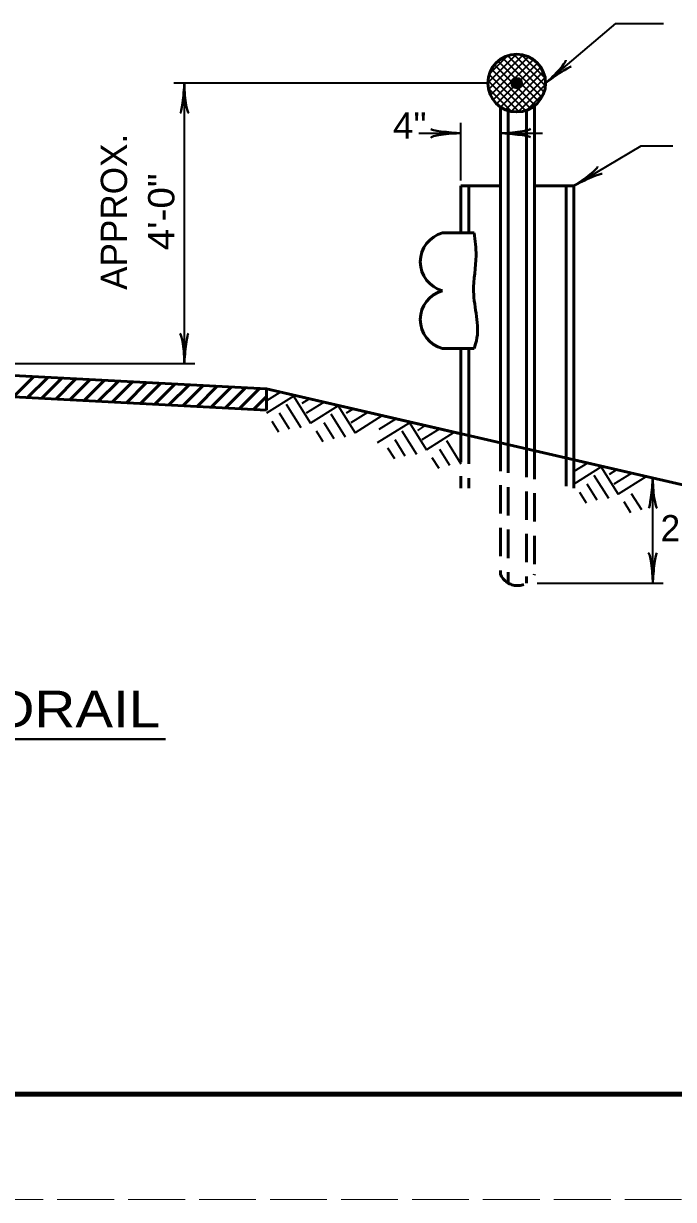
# Model space of a CAD drawing. Extents: x -54 to 626, y -41 to 399.
# Drawn here: x 117.5 to 179.4, y -41.3 to 70.7 of the extents above; entities that cross this region are included whole.
import ezdxf
from ezdxf.enums import TextEntityAlignment as Align

# ---------------------------------------------------------------- set-up
doc = ezdxf.new("R2010")
doc.units = 0
doc.header["$LTSCALE"] = 0.9
doc.linetypes.add('LONG_DASHED', pattern=[7.5, 6, -1.5])
doc.linetypes.add('MEDIUM_DASHED', pattern=[4.5, 3, -1.5])
doc.layers.add('1', color=7, linetype='Continuous', lineweight=35)
doc.layers.add('61', color=7, linetype='Continuous', lineweight=35)

msp = doc.modelspace()

# ---------------------------------------------------------------- hatches: boundary and pattern name
at = {"layer": '1'}
msp.add_hatch(color=256, dxfattribs=at).paths.add_polyline_path([(164.964, 64.9796, 1), (163.964, 64.9796, 1)])

# ---------------------------------------------------------------- linework, layer by layer
for p, q in [((161.7149, 65.008), (164.4343, 67.7274)), ((161.7842, 64.3702), (165.0726, 67.6585)), ((161.8652, 65.8653), (163.5791, 67.5793)), ((161.9649, 63.8438), (165.5998, 67.4786)), ((162.2211, 63.3928), (166.0515, 67.2232)), ((166.8579, 63.6317), (163.117, 67.3726)), ((167.0724, 64.1243), (163.6083, 67.5883)), ((167.1966, 64.7073), (164.1904, 67.7133)), ((167.1702, 65.4407), (164.925, 67.6859)), ((165.7922, 62.5759), (162.0594, 66.3088)), ((166.2133, 62.862), (162.3472, 66.7282)), ((162.5482, 63.0129), (166.4304, 66.8951)), ((166.5676, 63.2148), (162.6985, 67.084)), ((162.9379, 62.6955), (166.7488, 66.5063)), ((166.5714, 66.7737), (166.2742, 67.0709)), ((161.714, 64.9796), (131.843, 64.9796)), ((132.843, 38.2649), (132.843, 64.9796)), ((164.7103, 62.2437), (161.7292, 65.2248)), ((165.2973, 62.3638), (161.8485, 65.8127)), ((163.3981, 62.4485), (166.9946, 66.0451)), ((163.9414, 62.2847), (167.1589, 65.5023)), ((163.9671, 62.2798), (161.7643, 64.4826)), ((164.6018, 62.238), (167.2062, 64.8424)), ((165.5366, 62.4877), (167.0281, 63.9792)), ((159.1594, 55.7112), (159.1594, 61.2112)), ((155.1594, 60.2112), (159.1594, 60.2112)), ((162.9094, 60.2112), (166.9094, 60.2112)), ((96.2767, 38.2649), (133.843, 38.2649)), ((141.9227, 35.5312), (140.6464, 34.7338)), ((143.3063, 35.2118), (140.6464, 33.5497)), ((143.2088, 35.2343), (144.8576, 32.5958)), ((144.6899, 34.8924), (144.0137, 34.4532)), ((142.5252, 34.4069), (143.9236, 32.1957)), ((146.093, 34.5685), (144.4379, 33.5343)), ((147.4766, 34.2491), (144.8576, 32.5958)), ((147.4766, 34.2491), (149.0803, 31.6825)), ((148.8602, 33.9296), (148.2365, 33.5399)), ((150.2632, 33.6057), (148.6802, 32.6164)), ((141.1669, 32.791), (141.8159, 31.7791)), ((141.861, 33.575), (142.8202, 32.0398)), ((146.1033, 32.6572), (147.0626, 31.122)), ((146.7674, 33.4891), (148.1464, 31.2823)), ((151.6469, 33.2862), (149.0803, 31.6825)), ((154.3167, 32.6699), (151.1744, 30.7064)), ((152.9331, 32.9893), (151.3499, 32.0001)), ((154.2192, 32.6924), (155.8679, 30.0539)), ((145.3897, 31.8777), (146.0342, 30.8463)), ((153.5356, 31.865), (154.934, 29.6537)), ((155.7002, 32.3505), (155.0242, 31.9113)), ((157.1033, 32.0265), (155.4483, 30.9923)), ((158.487, 31.7071), (155.8679, 30.0539)), ((152.1772, 30.2491), (152.8262, 29.2372)), ((152.8714, 31.0331), (153.8307, 29.4979)), ((157.7778, 30.9472), (159.1594, 28.7362)), ((156.4001, 29.3357), (157.0446, 28.3043)), ((157.1137, 30.1152), (158.0729, 28.5801)), ((171.1866, 28.7752), (169.9094, 27.9772)), ((172.5702, 28.4558), (169.9094, 26.7933)), ((172.4727, 28.4783), (174.1214, 25.8397)), ((173.9537, 28.1363), (173.2777, 27.6973)), ((171.7891, 27.6509), (173.1875, 25.4397)), ((175.3569, 27.8124), (173.7018, 26.7782)), ((176.7405, 27.493), (174.1214, 25.8397)), ((177.4094, 17.3654), (177.4094, 27.3796)), ((170.4307, 26.035), (171.0797, 25.0231)), ((171.1249, 26.819), (172.0842, 25.2838)), ((175.3672, 25.9011), (176.3264, 24.366)), ((174.6536, 25.1217), (175.298, 24.0902)), ((166.4094, 17.3654), (178.4094, 17.3654))]:
    msp.add_line(p, q, dxfattribs=at)
at = {"layer": '1', "lineweight": 53}
for p, q in [((166.1594, 29.9768), (166.1594, 62.8144)), ((162.9094, 30.7272), (162.9094, 62.7112)), ((163.6594, 30.554), (163.6594, 62.3499)), ((165.4094, 30.15), (165.4094, 62.3972)), ((159.1594, 55.2112), (162.9094, 55.2112)), ((159.1594, 50.7112), (159.1594, 55.2112)), ((159.9094, 50.7112), (159.9094, 55.2112)), ((166.1594, 55.2112), (169.9094, 55.2112)), ((169.1594, 29.2843), (169.1594, 55.2112)), ((169.9094, 29.1111), (169.9094, 55.2112)), ((157.4094, 50.7112), (160.4094, 50.7112)), ((157.4094, 39.7112), (160.4094, 39.7112)), ((159.1594, 31.5929), (159.1594, 39.7112)), ((159.9094, 31.4198), (159.9094, 39.7112)), ((93.8158, 38.3083), (140.6464, 35.8671)), ((116.5869, 35.1065), (118.5019, 37.0214)), ((140.6464, 33.8456), (93.8156, 36.2998)), ((117.9307, 35.0361), (119.846, 36.9513)), ((119.2745, 34.9657), (121.1902, 36.8813)), ((120.6183, 34.8952), (122.5343, 36.8113)), ((121.9621, 34.8248), (123.8785, 36.7412)), ((123.3059, 34.7543), (125.2226, 36.6711)), ((124.6497, 34.6839), (126.5667, 36.601)), ((125.9934, 34.6135), (127.9109, 36.531)), ((127.3372, 34.5431), (129.2551, 36.4609)), ((128.681, 34.4727), (130.5992, 36.3908)), ((130.0248, 34.4023), (131.9433, 36.3207)), ((131.3686, 34.3318), (133.2875, 36.2507)), ((132.7124, 34.2614), (134.6317, 36.1806)), ((134.0562, 34.191), (135.9758, 36.1106)), ((135.4, 34.1205), (137.3199, 36.0405)), ((136.7438, 34.0501), (138.6641, 35.9704)), ((138.0876, 33.9797), (140.0083, 35.9003)), ((140.6455, 35.8672), (159.1594, 31.5929)), ((140.6464, 33.8456), (140.6464, 35.8671)), ((140.6464, 35.867), (176.5165, 27.5857)), ((139.4313, 33.9093), (140.6464, 35.1243))]:
    msp.add_line(p, q, dxfattribs=at)
at = {"layer": '1', "linetype": 'MEDIUM_DASHED', "lineweight": 53}
for p, q in [((159.1594, 31.5929), (159.1594, 26.4198)), ((159.9094, 31.4198), (159.9094, 26.4198)), ((162.9094, 30.7272), (162.9094, 18.2272)), ((163.6594, 30.554), (163.6594, 17.3654)), ((165.4094, 30.15), (165.4094, 17.3654)), ((166.1594, 29.9768), (166.1594, 18.2272)), ((169.1594, 29.2843), (169.1594, 26.4198)), ((169.9094, 29.1111), (169.9094, 26.4198))]:
    msp.add_line(p, q, dxfattribs=at)
at = {"layer": '1', "lineweight": 40}
msp.add_line((34.2753, 2.5087), (131.065, 2.5087), dxfattribs=at)
at = {"layer": '1'}
for points in [[(167.214, 64.9796), (173.8878, 70.655), (178.4295, 70.655)], [(169.9094, 55.2112), (176.294, 59.0048), (179.3203, 59.0048)]]:
    msp.add_lwpolyline(points, dxfattribs=at)
at = {"layer": '1', "lineweight": 53}
msp.add_lwpolyline([(169.9094, 29.1112), (176.5165, 27.5857), (212.636, 19.2467)], dxfattribs=at)
msp.add_circle((164.464, 64.9796), 2.75, dxfattribs=at)
at = {"layer": '1'}
msp.add_circle((164.464, 64.9796), 0.5, dxfattribs=at)
at = {"layer": '1', "lineweight": 53}
for centre in [(158.1376, 47.9612), (158.1376, 42.4612)]:
    msp.add_arc(centre, 2.8448, 104.83216, 255.16784, dxfattribs=at)
at = {"layer": '1', "linetype": 'MEDIUM_DASHED', "lineweight": 53}
msp.add_arc((164.5344, 18.8842), 1.7528, 202.01371, 337.98629, dxfattribs=at)
at = {"layer": '1', "lineweight": 40}
for centre, major_axis, ratio, start_param, end_param in [((167.8663, 65.897), (-1.2592, -1.2758), 0.122415, 0.89635335, 3.14159265), ((167.8663, 65.897), (-1.2592, -1.2758), 0.122415, 0.89635335, 3.14159265), ((168.2047, 65.5443), (-1.4518, -1.0041), 0.07063, 3.14071475, 5.41810995), ((168.2047, 65.5443), (-1.4518, -1.0041), 0.07063, 3.14071475, 5.41810995), ((132.6314, 63.8591), (0.1757, 1.7565), 0.07063, 3.14071475, 5.41810995), ((133.1193, 63.8884), (-0.1562, 1.7857), 0.122415, 0.89635335, 3.14159265), ((158.0389, 60.4228), (1.7565, -0.1757), 0.07063, 3.14071475, 5.41810995), ((158.0389, 60.4228), (1.7565, -0.1757), 0.07063, 3.14071475, 5.41810995), ((164.0006, 60.4875), (-1.7857, -0.1562), 0.122415, 0.89635335, 3.14159265), ((158.0682, 59.9349), (1.7857, 0.1562), 0.122415, 0.89635335, 3.14159265), ((158.0682, 59.9349), (1.7857, 0.1562), 0.122415, 0.89635335, 3.14159265), ((164.0299, 59.9996), (-1.7565, 0.1757), 0.07063, 3.14071475, 5.41810995), ((170.7064, 56.0061), (-1.4554, -1.0464), 0.122415, 0.89635335, 3.14159265), ((170.9808, 55.6016), (-1.5997, -0.7462), 0.07063, 3.14071475, 5.41810995), ((132.5667, 39.3561), (0.1562, -1.7857), 0.122415, 0.89635335, 3.14159265), ((133.0546, 39.3854), (-0.1757, -1.7565), 0.07063, 3.14071475, 5.41810995), ((177.1978, 26.2591), (0.1757, 1.7565), 0.07063, 3.14071475, 5.41810995), ((177.1978, 26.2591), (0.1757, 1.7565), 0.07063, 3.14071475, 5.41810995), ((177.6857, 26.2884), (-0.1562, 1.7857), 0.122415, 0.89635335, 3.14159265), ((177.6857, 26.2884), (-0.1562, 1.7857), 0.122415, 0.89635335, 3.14159265), ((177.1331, 18.4566), (0.1562, -1.7857), 0.122415, 0.89635335, 3.14159265), ((177.621, 18.4859), (-0.1757, -1.7565), 0.07063, 3.14071475, 5.41810995)]:
    msp.add_ellipse(centre, major_axis=major_axis, ratio=ratio, start_param=start_param, end_param=end_param, dxfattribs=at)
at = {"layer": '1', "lineweight": 53}
msp.add_spline([(160.4094, 50.7112), (160.5986, 48.5575), (160.3612, 45.1443), (160.6283, 40.4253), (160.4094, 39.7112)], degree=3, dxfattribs=at)
at = {"layer": '61', "lineweight": 158}
msp.add_line((614.7178, -31.3361), (-24.3422, -31.3161), dxfattribs=at)
at = {"layer": '61', "linetype": 'LONG_DASHED', "lineweight": 13}
msp.add_line((625.6577, -41.3161), (-54.4022, -41.3361), dxfattribs=at)

# ---------------------------------------------------------------- texts
at = {"layer": '1', "width": 1.05}
msp.add_text('4"', height=2.5, dxfattribs=at).set_placement((152.6883, 59.6877))
at = {"layer": '1'}
msp.add_text('APPROX.', height=2.5, rotation=90, dxfattribs=at).set_placement((127.3932, 52.7186), align=Align.CENTER)
at = {"layer": '1', "width": 1.1}
msp.add_text('4\'-0"', height=2.5, rotation=90, dxfattribs=at).set_placement((131.8932, 52.7187), align=Align.CENTER)
at = {"layer": '1'}
msp.add_text("2' MIN.", height=2.5, dxfattribs=at).set_placement((178.154, 21.3444))
at = {"layer": '1', "width": 1.15}
msp.add_text('TYPICAL SECTION WITH GUARDRAIL', height=3.5, dxfattribs=at).set_placement((82.5526, 3.6172), align=Align.CENTER)

doc.saveas('drawing.dxf')
